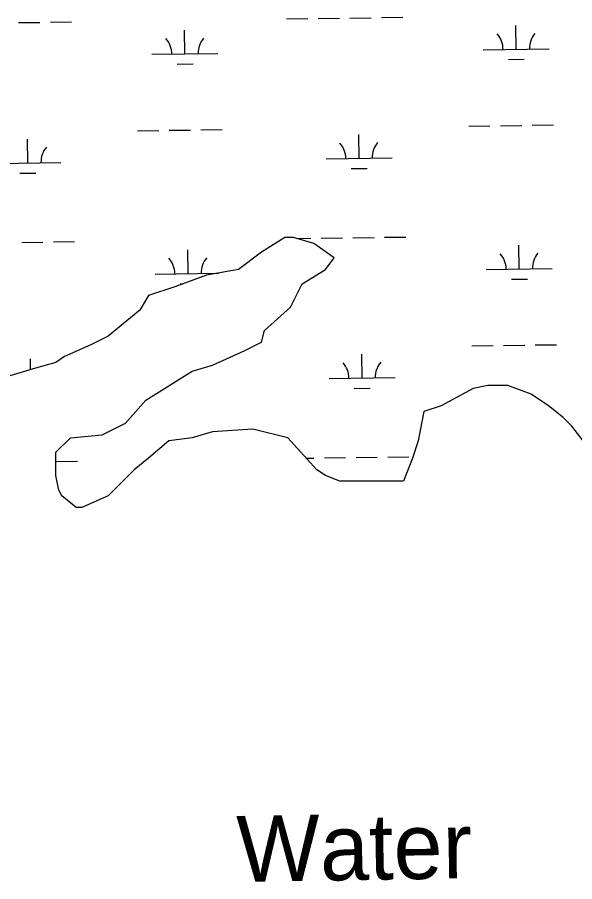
# Model space of a CAD drawing. Extents: x 3767014 to 3805179, y 361544 to 387384.
# Drawn here: x 3774905 to 3775749, y 368813 to 370122 of the extents above; entities that cross this region are included whole.
import ezdxf

# ---------------------------------------------------------------- set-up
doc = ezdxf.new("R2010")
doc.units = 0
for name, color, linetype in [('V-RIVR-IDEN', 7, 'Continuous'), ('V-TOPO-SHOR', 7, 'Continuous'), ('V-WETL-SWMP', 7, 'Continuous')]:
    doc.layers.add(name, color=color, linetype=linetype)

msp = doc.modelspace()

# ---------------------------------------------------------------- linework, layer by layer
at = {"layer": 'V-TOPO-SHOR'}
msp.add_lwpolyline([(3775762.407, 369480.817), (3775744.846, 369502.782), (3775731.675, 369515.961), (3775709.723, 369533.533), (3775683.381, 369551.105), (3775648.258, 369564.284), (3775617.526, 369564.284), (3775595.574, 369559.891), (3775547.28, 369533.533), (3775520.938, 369524.747), (3775512.157, 369480.817), (3775503.377, 369454.459), (3775490.206, 369419.316), (3775393.618, 369419.316), (3775371.666, 369428.101), (3775358.495, 369436.887), (3775314.592, 369485.21), (3775261.908, 369498.389), (3775200.443, 369493.996), (3775169.711, 369485.21), (3775134.588, 369480.817), (3775103.856, 369454.459), (3775081.904, 369436.888), (3775042.391, 369397.351), (3775002.878, 369379.779), (3774994.097, 369379.779), (3774972.145, 369397.351), (3774967.755, 369406.137), (3774963.364, 369428.102), (3774963.364, 369463.245), (3774985.316, 369485.21), (3775033.61, 369489.603), (3775068.733, 369507.175), (3775099.465, 369542.319), (3775169.711, 369586.249), (3775200.443, 369595.035), (3775248.737, 369617), (3775275.079, 369630.179), (3775279.469, 369647.751), (3775318.983, 369682.894), (3775336.544, 369718.038), (3775371.667, 369740.003), (3775384.838, 369757.575), (3775354.105, 369779.54), (3775323.373, 369788.326), (3775310.202, 369788.326), (3775275.079, 369766.361), (3775239.956, 369740.003), (3775191.663, 369731.217), (3775143.369, 369713.645), (3775103.856, 369700.466), (3775090.685, 369678.501), (3775042.391, 369638.965), (3775016.049, 369625.786), (3774976.536, 369608.214), (3774963.364, 369599.428), (3774932.632, 369590.642), (3774888.729, 369577.463)], dxfattribs=at)
at = {"layer": 'V-WETL-SWMP'}
for p, q in [((3774906.94, 370113.743), (3774938.937, 370114.188)), ((3774954.935, 370114.41), (3774986.932, 370114.855)), ((3775312.809, 370119.381), (3775344.806, 370119.826)), ((3775360.804, 370120.048), (3775392.801, 370120.493)), ((3775408.799, 370120.715), (3775440.796, 370121.159)), ((3775456.795, 370121.382), (3775488.792, 370121.826)), ((3775158.936, 370066.497), (3775158.436, 370102.494)), ((3775660.796, 370073.468), (3775660.296, 370109.465)), ((3775610.801, 370072.774), (3775710.791, 370074.163)), ((3775108.941, 370065.803), (3775208.931, 370067.192)), ((3775649.011, 370057.872), (3775673.009, 370058.206)), ((3775147.152, 370050.901), (3775171.149, 370051.234)), ((3775588.998, 369957.028), (3775620.995, 369957.472)), ((3775636.994, 369957.695), (3775668.991, 369958.139)), ((3775684.989, 369958.361), (3775716.986, 369958.806)), ((3775087.139, 369950.057), (3775119.136, 369950.501)), ((3775135.134, 369950.723), (3775167.131, 369951.168)), ((3775183.129, 369951.39), (3775215.126, 369951.834)), ((3775422.595, 369908.282), (3775422.095, 369944.278)), ((3774920.736, 369901.311), (3774920.236, 369937.307)), ((3774870.741, 369900.616), (3774970.731, 369902.005)), ((3775372.6, 369907.587), (3775472.591, 369908.976)), ((3775410.811, 369892.686), (3775434.809, 369893.019)), ((3774908.951, 369885.714), (3774932.949, 369886.048)), ((3775328.393, 369786.891), (3775349.426, 369787.183)), ((3775365.425, 369787.405), (3775397.422, 369787.85)), ((3775413.42, 369788.072), (3775445.417, 369788.516)), ((3775461.416, 369788.739), (3775493.412, 369789.183)), ((3774911.561, 369781.1), (3774943.557, 369781.545)), ((3774959.556, 369781.767), (3774991.553, 369782.212)), ((3775163.557, 369733.854), (3775163.057, 369769.851)), ((3775665.417, 369740.826), (3775664.917, 369776.822)), ((3775113.562, 369733.16), (3775209.68, 369734.495)), ((3775615.422, 369740.131), (3775715.412, 369741.52)), ((3775151.773, 369718.258), (3775156.217, 369718.32)), ((3775653.632, 369725.229), (3775677.63, 369725.563)), ((3775641.614, 369625.052), (3775673.611, 369625.496)), ((3775689.61, 369625.718), (3775721.607, 369626.163)), ((3775593.619, 369624.385), (3775625.616, 369624.83)), ((3774925.083, 369588.376), (3774924.857, 369604.664)), ((3775427.216, 369575.639), (3775426.716, 369611.636)), ((3775377.221, 369574.945), (3775477.211, 369576.334)), ((3775415.432, 369560.043), (3775439.429, 369560.376)), ((3775418.041, 369455.429), (3775450.038, 369455.873)), ((3775466.036, 369456.096), (3775498.033, 369456.54)), ((3774964.177, 369449.124), (3774996.174, 369449.569)), ((3775342.601, 369454.381), (3775354.047, 369454.54)), ((3775370.046, 369454.762), (3775402.043, 369455.207))]:
    msp.add_line(p, q, dxfattribs=at)
msp.add_lwpolyline([(3775762.407, 369480.817), (3775744.846, 369502.782), (3775731.675, 369515.961), (3775709.723, 369533.533), (3775683.381, 369551.105), (3775648.258, 369564.284), (3775617.526, 369564.284), (3775595.574, 369559.891), (3775547.28, 369533.533), (3775520.938, 369524.747), (3775512.157, 369480.817), (3775503.377, 369454.459), (3775490.206, 369419.316), (3775393.618, 369419.316), (3775371.666, 369428.101), (3775358.495, 369436.887), (3775314.592, 369485.21), (3775261.908, 369498.389), (3775200.443, 369493.996), (3775169.711, 369485.21), (3775134.588, 369480.817), (3775103.856, 369454.459), (3775081.904, 369436.888), (3775042.391, 369397.351), (3775002.878, 369379.779), (3774994.097, 369379.779), (3774972.145, 369397.351), (3774967.755, 369406.137), (3774963.364, 369428.102), (3774963.364, 369463.245), (3774985.316, 369485.21), (3775033.61, 369489.603), (3775068.733, 369507.175), (3775099.465, 369542.319), (3775169.711, 369586.249), (3775200.443, 369595.035), (3775248.737, 369617), (3775275.079, 369630.179), (3775279.469, 369647.751), (3775318.983, 369682.894), (3775336.544, 369718.038), (3775371.667, 369740.003), (3775384.838, 369757.575), (3775354.105, 369779.54), (3775323.373, 369788.326), (3775310.202, 369788.326), (3775275.079, 369766.361), (3775239.956, 369740.003), (3775191.663, 369731.217), (3775143.369, 369713.645), (3775103.856, 369700.466), (3775090.685, 369678.501), (3775042.391, 369638.965), (3775016.049, 369625.786), (3774976.536, 369608.214), (3774963.364, 369599.428), (3774932.632, 369590.642), (3774888.729, 369577.463)], dxfattribs=at)
for centre, start, end in [((3775605.552, 370073.176), 0.024037, 41.567696), ((3775716.027, 370074.711), 140.024034, 181.567693), ((3775103.692, 370066.204), 0.024037, 41.567696), ((3775214.167, 370067.739), 140.024034, 181.567693), ((3775367.351, 369907.989), 0.024037, 41.567696), ((3775477.826, 369909.524), 140.024034, 181.567693), ((3774975.967, 369902.553), 140.024034, 181.567693), ((3775108.313, 369733.562), 0.024037, 41.567696), ((3775218.788, 369735.096), 140.024034, 181.567693), ((3775610.173, 369740.533), 0.024037, 41.567696), ((3775720.648, 369742.068), 140.024034, 181.567693), ((3775482.447, 369576.881), 140.024034, 181.567693), ((3775371.972, 369575.346), 0.024037, 41.567696)]:
    msp.add_arc(centre, 35.246, start, end, dxfattribs=at)

# ---------------------------------------------------------------- texts
at = {"layer": 'V-RIVR-IDEN'}
msp.add_text('Water', height=100, rotation=0.948572, dxfattribs=at).set_placement((3775237.844, 368812.635))

doc.saveas('drawing.dxf')
